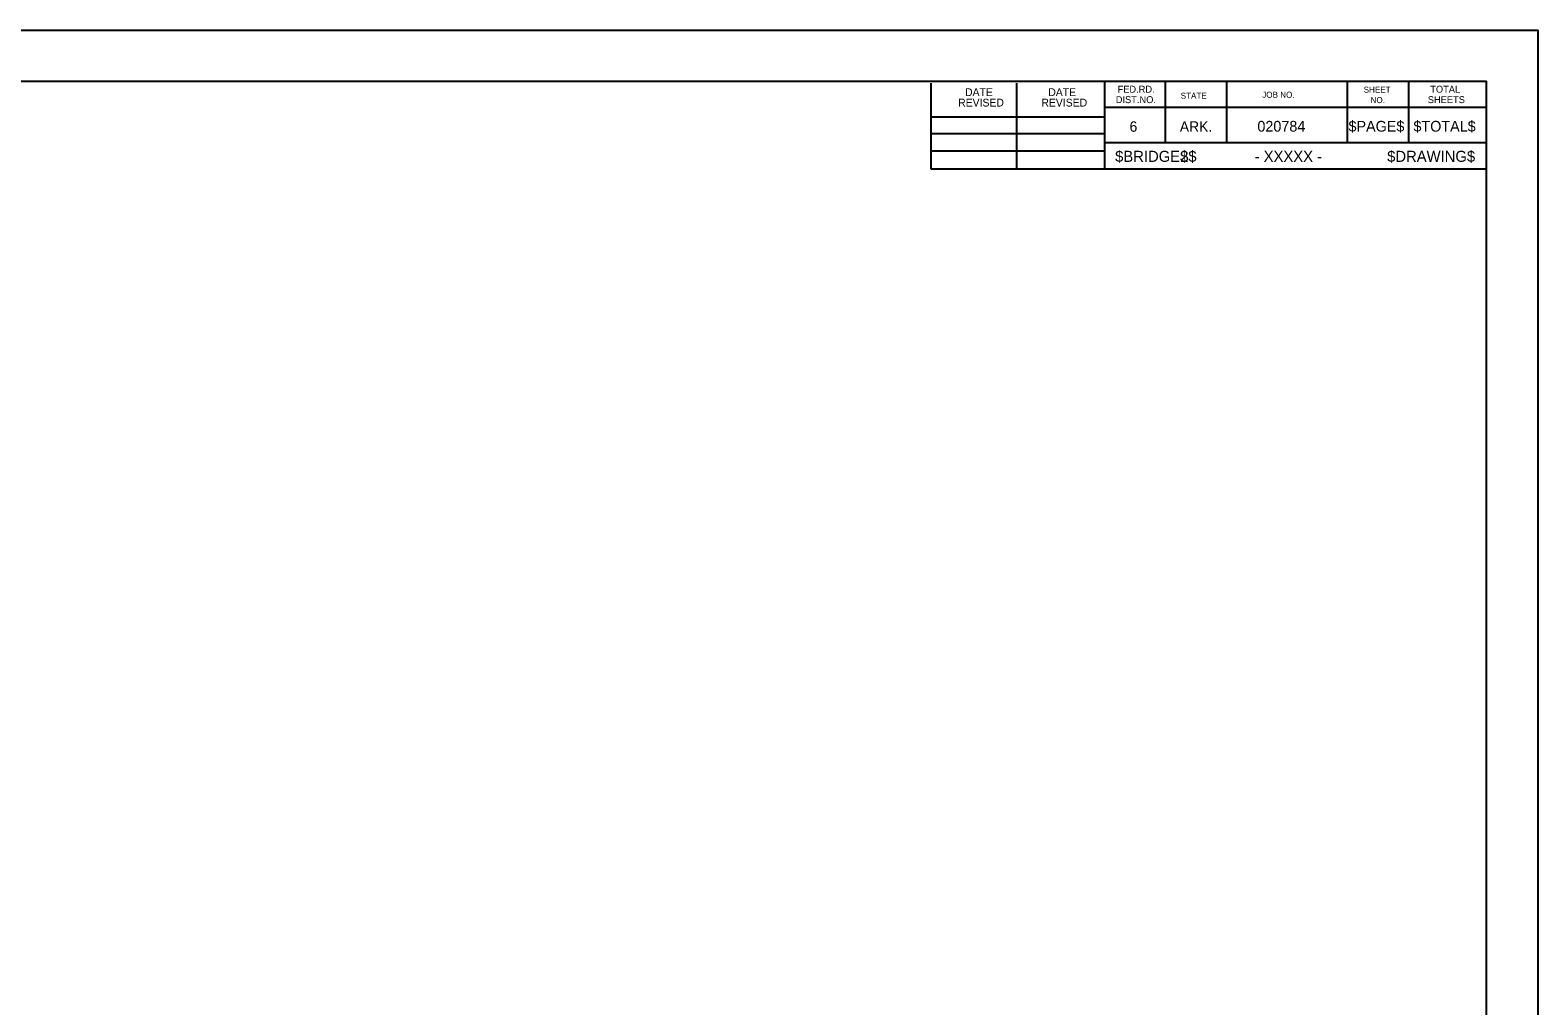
# Model space of a CAD drawing. Extents: x 16 to 1228743, y 11 to 152440.
# Drawn here: x 17.074 to 18.49, y 11.626 to 12.543 of the extents above; entities that cross this region are included whole.
import ezdxf

# ---------------------------------------------------------------- set-up
doc = ezdxf.new("R2010")
doc.units = 0
for name, color, linetype in [('B_Bridge1', 7, 'Continuous'), ('B_Bridge2', 7, 'Continuous'), ('B_Copy In', 7, 'Continuous'), ('R_Border', 7, 'Continuous')]:
    doc.layers.add(name, color=color, linetype=linetype)

msp = doc.modelspace()

# ---------------------------------------------------------------- linework, layer by layer
at = {"layer": 'R_Border'}
for p, q in [((15.7833, 12.4948), (18.4422, 12.4948)), ((17.9202, 12.4124), (17.9202, 12.4931)), ((18.0009, 12.4124), (18.0009, 12.4931)), ((18.0831, 12.4948), (18.0831, 12.4124)), ((18.1401, 12.4948), (18.1401, 12.4369)), ((18.1979, 12.4948), (18.1979, 12.4369)), ((18.3111, 12.4948), (18.3111, 12.4369)), ((18.3689, 12.4948), (18.3689, 12.4369)), ((18.4422, 10.7576), (18.4422, 12.4948)), ((18.4422, 12.4703), (18.0831, 12.4703)), ((18.4422, 12.4704), (18.4422, 12.4704)), ((17.9202, 12.4613), (18.0831, 12.4613)), ((17.9202, 12.4458), (18.0831, 12.4458)), ((17.9202, 12.4296), (18.0831, 12.4296)), ((18.4422, 12.4369), (18.0831, 12.4369)), ((18.4422, 12.4124), (17.9202, 12.4124))]:
    msp.add_line(p, q, dxfattribs=at)
msp.add_lwpolyline([(15.657, 12.5428), (18.4903, 12.5428), (18.4903, 10.7095), (15.657, 10.7095)], close=True, dxfattribs=at)

# ---------------------------------------------------------------- texts
at = {"layer": 'B_Bridge1'}
msp.add_text('$BRIDGE$', height=0.0104, dxfattribs=at).set_placement((18.0931, 12.4191))
at = {"layer": 'B_Bridge2'}
msp.add_text('$BRIDGE2$', height=0.0104, dxfattribs=at).set_placement((18.0931, 12.4191))
at = {"layer": 'B_Copy In'}
msp.add_text('- XXXXX -', height=0.0104, dxfattribs=at).set_placement((18.2242, 12.4191))
at = {"layer": 'R_Border'}
for s, height, p in [('DATE', 0.00733, (17.9521, 12.4809)), ('DATE', 0.00733, (18.0303, 12.4809)), ('DIST.NO.', 0.00652, (18.0937, 12.4743)), ('FED.RD.', 0.00652, (18.0954, 12.4841)), ('STATE', 0.0057, (18.1547, 12.4784)), ('JOB NO.', 0.0057, (18.2313, 12.4793)), ('SHEET', 0.0057, (18.3266, 12.4841)), ('SHEETS', 0.00652, (18.3869, 12.4743)), ('TOTAL', 0.00652, (18.3892, 12.4841)), ('REVISED', 0.00733, (17.9456, 12.4711)), ('REVISED', 0.00733, (18.0238, 12.4711)), ('NO.', 0.0057, (18.3331, 12.4743)), ('6', 0.00977, (18.1067, 12.4474)), ('ARK.', 0.00977, (18.1539, 12.4474)), ('020784', 0.01009, (18.2268, 12.4475)), ('$PAGE$', 0.01009, (18.3124, 12.4475)), ('$TOTAL$', 0.01009, (18.3734, 12.4475)), ('$DRAWING$', 0.0104, (18.3487, 12.4191))]:
    msp.add_text(s, height=height, dxfattribs=at).set_placement(p)

doc.saveas('drawing.dxf')
